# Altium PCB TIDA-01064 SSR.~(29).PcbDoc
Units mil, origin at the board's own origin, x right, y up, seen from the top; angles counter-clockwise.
Board outline 2700 x 2000 mil, 2 copper layers (Top Layer, Bottom Layer), stack 62 mil thick; 76 components, 26 nets, 146 pads, 43 vias.
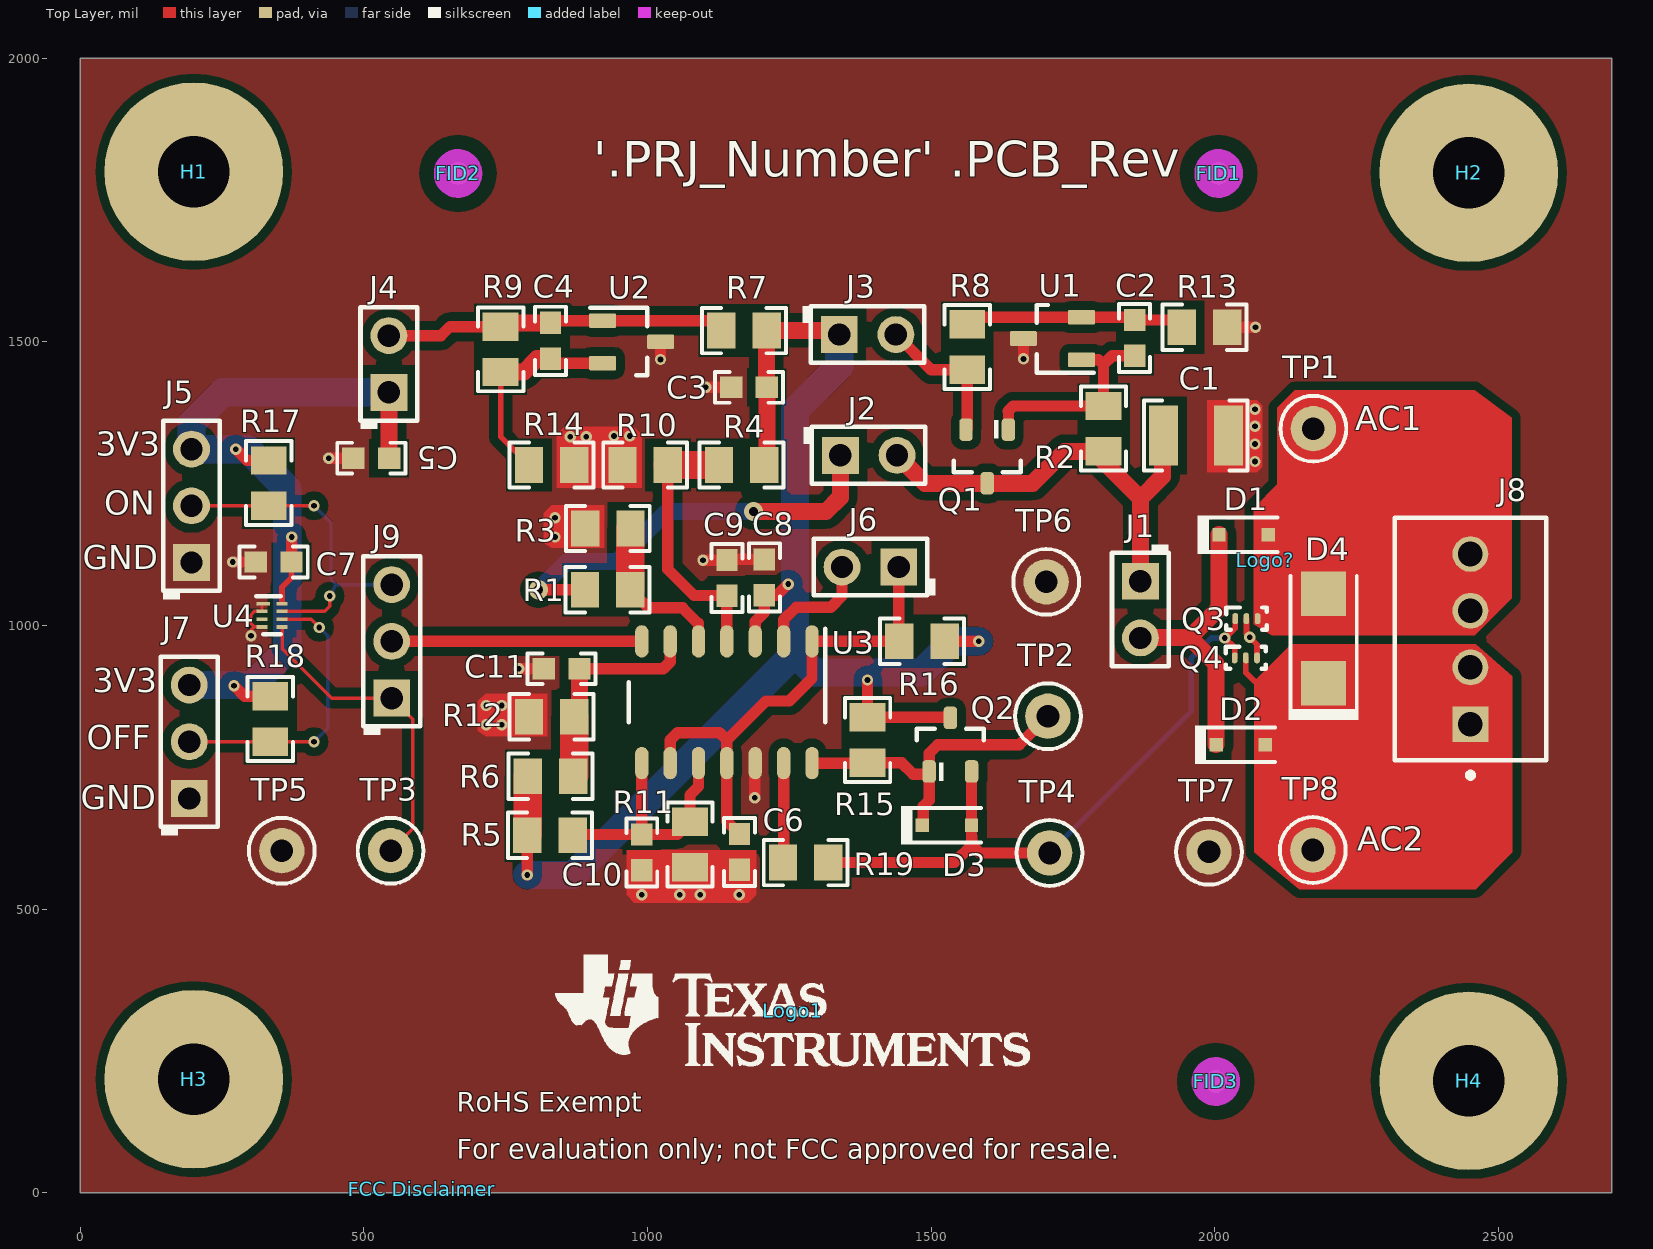
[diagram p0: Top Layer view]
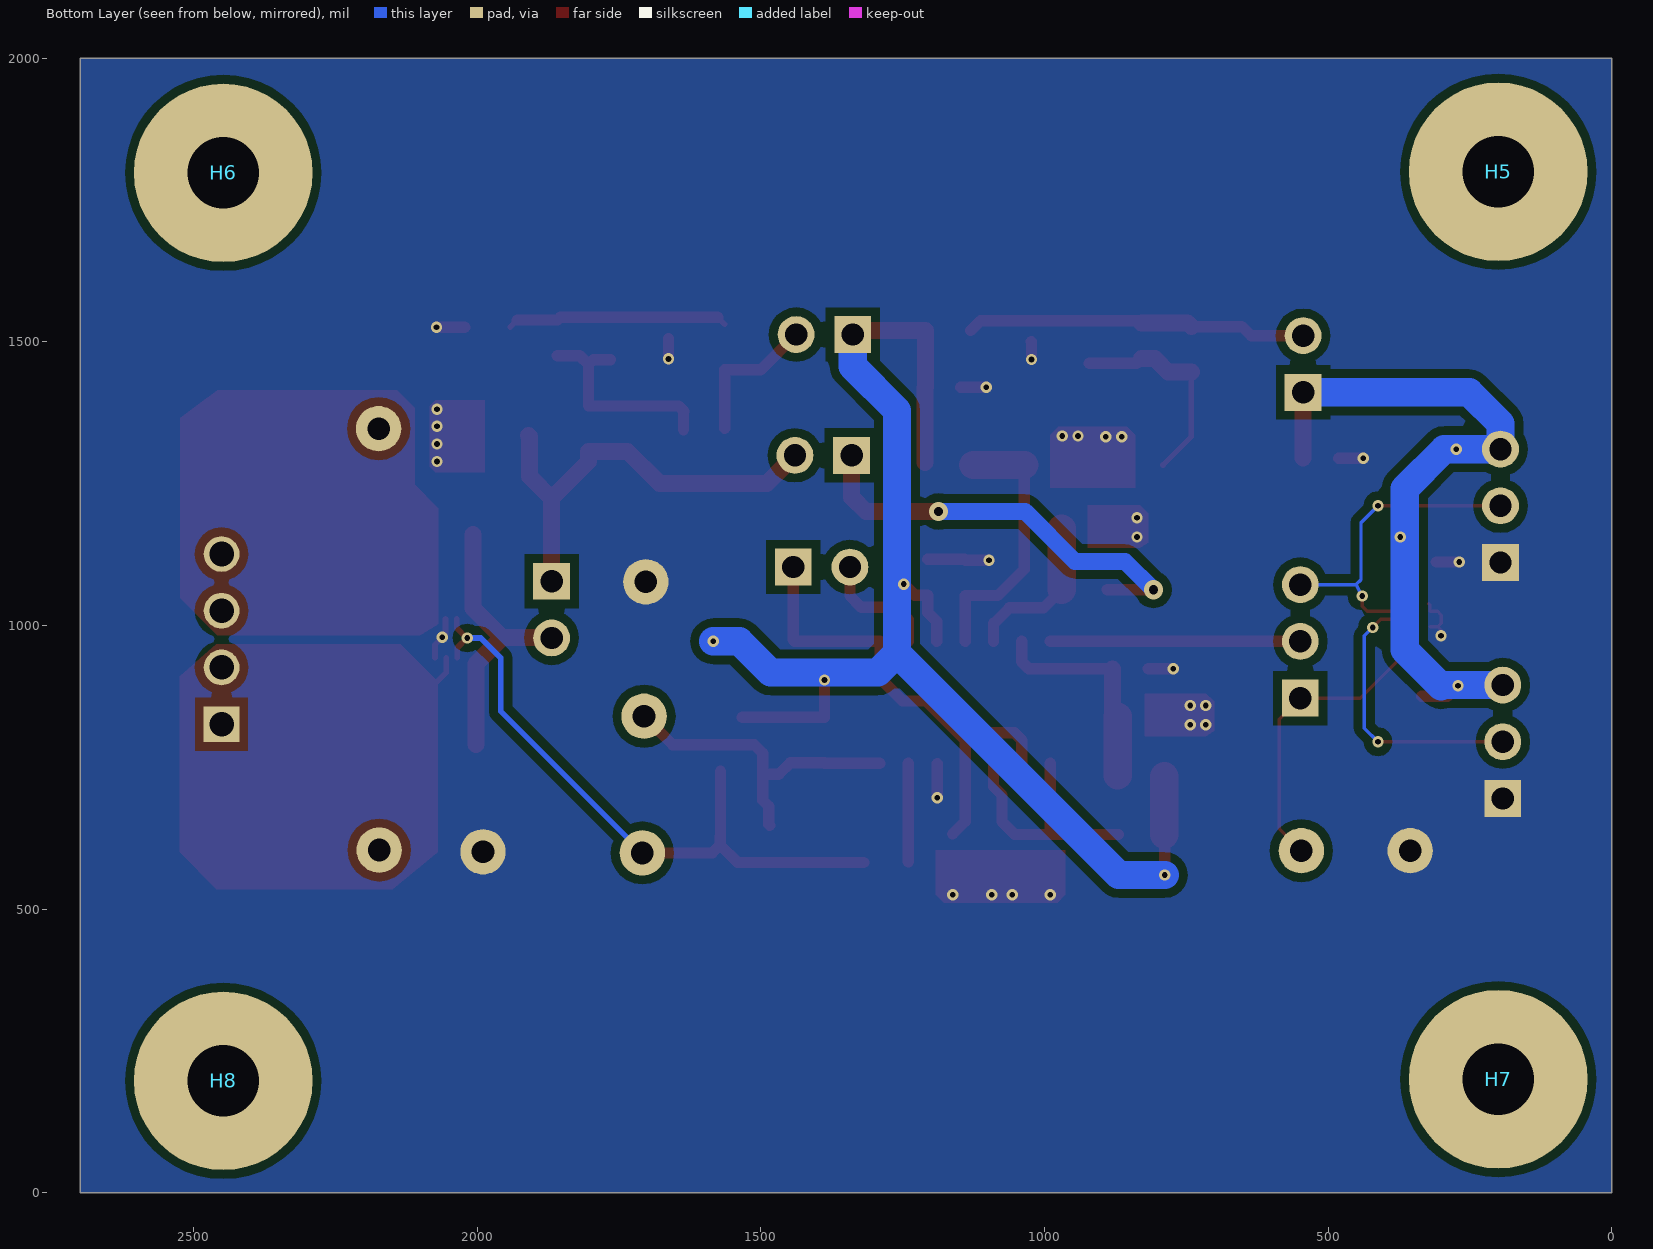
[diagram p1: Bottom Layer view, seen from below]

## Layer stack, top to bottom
Top Solder: solder mask 0.4, Solder Resist, Dk 3.5
Top Layer: signal copper 1.4
Dielectric1: core 59.2, FR-4, Dk 4.8
Bottom Layer: signal copper 1.4
Bottom Solder: solder mask 0.4, Solder Resist, Dk 3.5

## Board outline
0,0 2700,0 2700,2000 0,2000

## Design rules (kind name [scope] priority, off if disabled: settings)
AcuteAngle [All] p1: minimum=4.50000000000000E+0001 checktracksonly=FALSE
AssemblyTestPointUsage [All] p1: valid=2
Clearance Clearance_BoardEdge_MountingHoles [OnCopper and InComponentClass('Mounting Holes') vs IsKeepOut] p1: gap=25
Clearance Clearance_BoardEdge_Poly [OnCopper and InPoly vs IsKeepOut] p2: gap=25
Clearance Clearance_BoardEdge [OnCopper and Not InComponentClass('Logo') and not InComponentClass('FiducialMark') and not InRegion(1000,500,4000,800) and Not IsKeepout vs IsKeepOut] p3: gap=25
Clearance Clearance_Poly [InPolygon] p4: gap=15
Clearance [All] p5: gap=7
ComponentClearance ComponentClearance_Shunt [InComponentClass('Header') vs InComponentClass('Shunt')] p1: gap=0 collisioncheckmode=3 verticalgap=0 showdistances=FALSE
ComponentClearance ComponentClearance_Logo [InComponentClass('Logo')] p2: gap=50 collisioncheckmode=3 verticalgap=10 showdistances=FALSE
ComponentClearance ComponentClearance_ScrewToNut [(HasFootprint('NY PMS 440 0025 PH')) vs (HasFootprint('Keystone_1902C'))] p3: gap=5 collisioncheckmode=3 verticalgap=10 showdistances=FALSE
ComponentClearance ComponentClearance_MountingHoles [InComponentClass('Mounting Holes')] p4: gap=250 collisioncheckmode=3 verticalgap=100000 showdistances=FALSE
ComponentClearance ComponentClearance_SmallPassives [HasFootprint('0201*') or HasFootprint('0402*') or HasFootprint('0508') or HasFootprint('0603*') or HasFootprint('0612') or HasFootprint('0805*') or HasFootprint('0815*') or HasFootprint('0830*') or HasFootprint('1206*') or HasFootprint('1210*') or HasFootprint('1808*') or HasFootprint('1812*') or HasFootprint('1825*') or HasFootprint('2010*') or HasFootprint('2220*') or HasFootprint('2225*') or HasFootprint('2512*') or HasFootprint('2728*') or HasFootprint('3518*') vs HasFootprint('0201*') or HasFootprint('0402*') or HasFootprint('0508') or HasFootprint('0603*') or HasFootprint('0612') or HasFootprint('0805*') or HasFootprint('0815*') or HasFootprint('0830*') or HasFootprint('1206*') or HasFootprint('1210*') or HasFootprint('1808*') or HasFootprint('1812*') or HasFootprint('1825*') or HasFootprint('2010*') or HasFootprint('2220*') or HasFootprint('2225*') or HasFootprint('2512*') or HasFootprint('2728*') or HasFootprint('3518*')] p5: gap=15 collisioncheckmode=3 verticalgap=10 showdistances=FALSE
ComponentClearance ComponentClearance_THtoSMT [IsThruComponent vs IsSMTComponent] p6: gap=50 collisioncheckmode=3 verticalgap=30 showdistances=FALSE
ComponentClearance ComponentClearance_THtoTH [IsThruComponent vs IsThruComponent] p7: gap=50 collisioncheckmode=3 verticalgap=30 showdistances=FALSE
ComponentClearance [All] p8: gap=40 collisioncheckmode=3 verticalgap=10 showdistances=FALSE
DiffPairsRouting [All] p1: maxlimit=100 minlimit=10 mostfreqgap=10 toplayer_minwidth=15 toplayer_maxwidth=15 toplayer_prefwidth=15 bottomlayer_minwidth=15 bottomlayer_maxwidth=15 bottomlayer_prefwidth=15 maxuncoupledlength=1000
FabricationTestPointUsage TestPointUsage [All] p1: valid=2 allowmultiple=FALSE
FabricationTestpoint Testpoint [All] p1: side=3 testpointundercomponent=TRUE minsize=40 maxsize=100 preferedsize=60 minholesize=0 maxholesize=40 preferedholesize=32 testpointgrid=1 allowsidetop=TRUE allowsidebottom=TRUE usegrid=TRUE gridtolerance=0.01
FanoutControl Fanout_LCC [IsLCC] p1: bgadir=Out bgaviamode=Centered fanoutstyle=Auto fanoutdirection=Alternating viagrid=1 // Fanout_LCC (Default Rule)
FanoutControl Fanout_BGA [IsBGA] p2: bgadir=Out bgaviamode=Centered fanoutstyle=Auto fanoutdirection=Alternating viagrid=1 // Fanout_BGA (Default Rule)
FanoutControl Fanout_Default [All] p4: bgadir=Out bgaviamode=Centered fanoutstyle=Auto fanoutdirection=Alternating viagrid=1 // Fanout_Default (Default Rule)
FanoutControl Fanout_Small [(CompPinCount < 5)] p5: bgadir=Out bgaviamode=Centered fanoutstyle=Auto fanoutdirection=OutThenIn viagrid=1 // Fanout_Small (Default Rule)
HoleSize [All] p1: absolutevalues=TRUE maxlimit=251 minlimit=8 maxpercent=80.000 minpercent=20.000
MinimumAnnularRing MinimumAnnularRing_ThermalPadVias [IsVia and InAnyComponent] p1: minimumring=5.91
MinimumAnnularRing [All] p2: minimumring=9
MinimumSolderMaskSliver MinimumSolderMaskSliver_Logo [InComponentClass('Logo') vs InComponentClass('Logo')] p1: minsoldermaskwidth=0.7
MinimumSolderMaskSliver [All] p2: minsoldermaskwidth=3.94
PlaneClearance [All] p1: clearance=15
PlaneConnect [All] p1: planeconnectstyle=Direct reliefexpansion=10 reliefentries=4 reliefconductorwidth=10 reliefairgap=10
PolygonConnect [All] p1: connectstyle=Direct reliefconductorwidth=10 reliefentries=4 polygonreliefangle="90 Angle" airgapwidth=10
RoutingVias ThermalPadVias [IsVia and InAnyComponent] p1: holewidth=7.87 width=19.68 viastyle="Through Hole" minholewidth=7.87 minwidth=19.68 maxholewidth=12.99 maxwidth=23.62
RoutingVias [All] p2: holewidth=16 width=34 viastyle="Through Hole" minholewidth=7.87 minwidth=26 maxholewidth=40 maxwidth=65
SMDToCorner [All] p1: distance=30000
SilkToBoardRegionClearance [Not ((IsComment or IsDesignator) And (Hide <> 'False')) and not InRegion(1000,500,4000,800)] p1:
SilkToSilkClearance [All] p1: silktosilkclearance=0
SilkToSolderMaskClearance SilkscreenOverComponentPads [IsPad] p1: minsilkscreentomaskgap=0 clearancetoexposedcopper=TRUE
SolderMaskExpansion [All] p1: expansion=1.97
Width [All] p1: maxlimit=100 minlimit=6 preferedwidth=10 checkconnectedcopper=TRUE
14 further rules are at their usual default settings.

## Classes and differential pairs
component class AssemblyNote: ZZ1 ZZ2 ZZ3
component class FiducialMark: FID1 FID2 FID3
component class "TIDA-01064 SSR_TID_Hardware": "FCC Disclaimer" FID1 FID2 FID3 H1 H2 H3 H4 H5 H6 H7 H8 Logo1 Logo? ZZ1 ZZ2 ZZ3
component class Logo: Logo1
component class "Mounting Holes": H1 H2 H3 H4
component class Header: J1 J2 J3 J4 J5 J6 J7 J9
component class "TIDA-01064 SSR_Relay": C1 C2 C3 C4 C5 C6 C7 C8 C9 C10 C11 D1 D2 D3 D4 J1 J2 J3 J4 J5 J6 J7 J8 J9 Q1 Q2 Q3 Q4 R1 R2 R3 R4 R5 R6 R7 R8 R9 R10 R11 R12 R13 R14 R15 R16 R17 R18 R19 TP1 TP2 TP3 TP4 TP5 TP6 TP7 TP8 U1 U2 U3 U4

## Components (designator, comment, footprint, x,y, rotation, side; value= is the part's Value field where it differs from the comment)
C1 "C3225X7S2A335M200AB" 1210 1967,1335 r0 top
C2 "GRM1885C1H201JA01D" 0603 1859,1507 r90 top
C3 "GRM188R61E105KA12D" 0603 1179,1420 r180 top
C4 "GRM1885C1H201JA01D" 0603 829,1502 r270 top
C5 "GRM188R61E105KA12D" 0603 513,1295 r180 top
C6 "GRM188R61E105KA12D" 0603 1162,601 r270 top
C7 "GRM188R71C104KA01D" 0603 341,1112 r0 top
C8 "GRM188R71C104KA01D" 0603 1206,1085 r270 top
C9 "GRM188R71C104KA01D" 0603 1140,1084 r270 top
C10 "GRM188R71C104KA01D" 0603 990,600 r90 top
C11 "GRM188R71C104KA01D" 0603 848.68,923.69 r0 top
D1 "1N4448WX-TP" sod-323 2051,1160 r0 top
D2 "1N4448WX-TP" sod-323 2046,790 r0 top
D3 "1N4448WX-TP" sod-323 1528,648 r0 top
D4 "SMAJ40CA" SMA 2192,977 r90 top
"FCC Disclaimer" "FCC disclaimer" FCC_disclaimer 603,7 r90 top
FID1 "Fiducial" Fiducial10-20 2007,1797 r0 top
FID2 "Fiducial" Fiducial10-20 666,1797 r0 top
FID3 "Fiducial" Fiducial10-20 2002,196 r0 top
H1 "NY PMS 440 0025 PH" "NY PMS 440 0025 PH" 200,1800 r0 top locked
H2 "NY PMS 440 0025 PH" "NY PMS 440 0025 PH" 2448,1798 r0 top locked
H3 "NY PMS 440 0025 PH" "NY PMS 440 0025 PH" 200,200 r0 top locked
H4 "NY PMS 440 0025 PH" "NY PMS 440 0025 PH" 2448,197 r0 top locked
H5 "1902C" Keystone_1902C 200,1800 r180 bottom locked
H6 "1902C" Keystone_1902C 2448,1798 r180 bottom locked
H7 "1902C" Keystone_1902C 200,200 r180 bottom locked
H8 "1902C" Keystone_1902C 2448,197 r180 bottom locked
J1 "5-146278-2" TE_5-146278-2 1869,1028 r270 top
J2 "5-146278-2" TE_5-146278-2 1390,1300 r0 top
J3 "5-146278-2" TE_5-146278-2 1388,1513 r0 top
J4 "5-146278-2" TE_5-146278-2 544,1461 r90 top
J5 "5-146278-3" TE_5-146278-3 196.02,1211 r90 top
J6 "5-146278-2" TE_5-146278-2 1393,1103 r180 top
J7 "5-146278-3" TE_5-146278-3 192.02,795 r90 top
J8 "282834-4" TEC_282834-4 2451,976 r90 top
J9 "5-146278-3" TE_5-146278-3 549,972 r90 top
Logo1 "Texas Instruments" TI_Stacked_Overlay_Small 1256,321 r0 top
Logo? "EU RoHS Exempt Logo" EURoHS_Exempt_60mil 2089,1115 r90 top
Q1 "MMBTA05LT1G" SOT-23 1599,1298 r270 top
Q2 "MMBT3904LT1G" SOT-23 1534,790 r90 top
Q3 "CSD18541F5" YJK0003A 2056,1012 r0 top
Q4 "CSD18541F5" YJK0003A 2055,943 r0 top
R1 "CRCW080510M0FKEA" 0805_HV 929.71,1063 r0 top
R2 "CRCW0805205KFKEA" 0805_HV 1804,1347 r270 top
R3 "CRCW08053M09FKEA" 0805_HV 930,1171 r0 top
R4 "CRCW080510M0FKEA" 0805_HV 1166,1283 r0 top
R5 "CRCW080510M0FKEA" 0805_HV 828,630 r180 top
R6 "RC0805JR-0733ML" 0805_HV 829,734 r180 top
R7 "CRCW0805100KFKEA" 0805_HV 1170,1520 r0 top
R8 "CRCW08053M74FKEA" 0805_HV 1564,1491 r270 top
R9 "CRCW0805806KFKEA" 0805_HV 741,1487 r90 top
R10 "CRCW08057M50FKEA" 0805_HV 996,1283 r0 top
R11 "CRCW08054M32FKEA" 0805_HV 1075,614 r90 top
R12 "CRCW08056M49FKEA" 0805_HV 831,839 r0 top
R13 "CRCW08051M30FKEA" 0805_HV 1982,1526 r180 top
R14 "CRCW08052M80FKEA" 0805_HV 831,1283 r180 top
R15 "CRCW080590K9FKEA" 0805_HV 1388,798 r90 top
R16 "CRCW08051M82FKEA" 0805_HV 1484,972 r0 top
R17 "CRCW0805124KFKEA" 0805_HV 332,1251 r90 top
R18 "CRCW0805124KFKEA" 0805_HV 335,835 r90 top
R19 "CRCW08050000Z0EA" 0805_HV 1279,582 r0 top
TP1 "5001" Keystone5001 2174,1347 r0 top
TP2 "5001" Keystone5001 1706,840 r0 top
TP3 "5001" Keystone5001 547.18,602.88 r0 top
TP4 "5001" Keystone5001 1709,599 r0 top
TP5 "5001" Keystone5001 355.18,602.88 r0 top
TP6 "5001" Keystone5001 1703,1077 r0 top
TP7 "5001" Keystone5001 1990,601 r0 top
TP8 "5001" Keystone5001 2173,604 r0 top
U1 "ATL431AIDBZR" DBZ0003A_M 1714,1506 r180 top
U2 "ATL431AIDBZR" DBZ0003A_M 972,1500 r0 top
U3 "LP339D" D0014A_N 1140,864.68 r270 top
U4 "SN74AUP1G74DQER" DQE0008A 338,1018 r0 top
ZZ1 "These assemblies are ESD sensitive, ESD precautions shall be observed." AssemblyNote 185,3829.11 r0 top
ZZ2 "These assemblies must be clean and free from flux and all contaminants. Use of no clean flux is not acceptable." AssemblyNote 185,3740.56 r0 top
ZZ3 "These assemblies must comply with workmanship standards IPC-A-610 Class 2, unless otherwise specified." AssemblyNote 185,3652 r0 top

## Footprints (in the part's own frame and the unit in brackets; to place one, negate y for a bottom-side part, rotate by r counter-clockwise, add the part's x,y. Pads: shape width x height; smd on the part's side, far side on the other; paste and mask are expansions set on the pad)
0603 [mm] "0603 from SM-752 data"
  rect 1x0.95 smd: 1(-0.8,0) 2(0.8,0)
  silkscreen extent -1.52,-0.69 1.52,0.69, body extent -0.87,-0.47 0.87,0.47, height 1
0805_HV [mil] "0805 with 30mil clearance between pads"
  rect 50x63 smd: 1(-40,0) 2(40,0)
  silkscreen extent -74,-40 74,40, body extent -43,-29 43,29, height 57
1210 [mm] "1210 from SM-752 data"
  rect 1.3x2.7 smd: 1(-1.45,0) 2(1.45,0)
  silkscreen extent -2.32,-1.57 2.32,1.57, body extent -1.7,-1.35 1.7,1.35, height 1.35
AssemblyNote [mil] "Assembly Note"
D0014A_N [mm] "SOIC, 14-Leads, Body 8.7x3.9mm, Pitch 1.27mm, IPC Medium Density"
  oval 1.45x0.6 smd: 1(-2.725,3.81) 2(-2.725,2.54) 3(-2.725,1.27) 4(-2.725,0) 5(-2.725,-1.27) 6(-2.725,-2.54) 7(-2.725,-3.81) 8(2.725,-3.81) 9(2.725,-2.54) 10(2.725,-1.27) 11(2.725,0) 12(2.725,1.27) 13(2.725,2.54) 14(2.725,3.81)
  silkscreen extent -3.3,-4.4 0.9,4.4, body extent -3.02,-4.32 3.02,4.32, height 1.6
DBZ0003A_M [mm] "SOT23, 3-Leads, Body 2.9x1.3mm, Pitch 0.95mm, Lead Span 2.4mm, IPC Low Density"
  rrect15% 1.2x0.65 smd: 1(-1.3,0.95) 2(-1.3,-0.95) 3(1.3,0)
  silkscreen extent -1.85,-1.5 0.7,1.53, body extent -1.26,-1.46 1.26,1.46, height 0.98
DQE0008A [mm] "SON, 8-Leads, Body 1.4x1mm, Pitch 0.35mm, TI Recommended"
  rect 0.6x0.16 smd mask+0: 1(-0.4,0.525)
  rect 0.5x0.16 smd mask+0: 2(-0.45,0.175) 3(-0.45,-0.175) 4(-0.45,-0.525) 5(0.45,-0.525) 6(0.45,-0.175) 7(0.45,0.175) 8(0.45,0.525)
  silkscreen extent -0.7,-0.85 0.4,0.85, body extent -0.53,-0.72 0.53,0.73, height 0.41
EURoHS_Exempt_60mil [mil] "EU RoHS Exempt symbol"
FCC_disclaimer [mil]
Fiducial10-20 [mm]
  round 1 smd mask+0.5: 1(0,0)
  Top Layer keep-out circle w1.178: c0,0 r0.5
Keystone5001 [mil] "For Keystone 500x miniature loop terminals"
  round 80 hole 40: 1(0,0)
  silkscreen extent -58,-58 58,58, body extent -49,-49 49,49, height 182
Keystone_1902C [mil] "Hex Standoff, 4-40 threaded, nylon"
  body extent -145,-126 146,126, height 501
"NY PMS 440 0025 PH" [mm] "4-40 nylon screw and mounting hole"
  round 8 hole 3.2: 1(0,0)
  body extent -3.3,-3.3 3.3,3.3, height 2.69
SMA [mm] "Molded Diode, 2-Leads, Body 4.3x2.6mm, IPC Medium Density, based on OnSemi component dimensions and land pattern"
  rect 2x2 smd: 1(-2,0) 2(2,0)
  silkscreen extent -3.66,-1.57 2.79,1.57, body extent -2.6,-1.3 2.6,1.3, height 2.42
sod-323 [mm] "NXP recommended land pattern"
  rect 0.6x0.6 smd paste-0.05: 1(-1.1,0) 2(1.1,0)
  silkscreen extent -2.06,-0.86 1.53,0.86, body extent -1.3,-0.67 1.3,0.68, height 1.1
SOT-23 [mm] "SOT23, 3-Leads, Body 2.9x1.3mm, Pitch 0.95mm, Lead Span 2.5mm, IPC Medium Density"
  rrect50% 1x0.6 smd: 1(-1.2,0.95) 2(-1.2,-0.95) 3(1.2,0)
  silkscreen extent -1.63,-1.5 0.7,1.5, body extent -1.16,-1.45 1.21,1.45, height 1
TE_5-146278-2 [mm] "TE CONNECTIVITY"
  rect 1.65x1.65 hole 1: 1(-1.27,0)
  round 1.65 hole 1: 2(1.27,0)
  silkscreen extent -2.92,-1.27 2.54,1.27, body extent -2.41,-1.17 2.41,1.17, height 8.13
TE_5-146278-3 [mm] "TE CONNECTIVITY"
  rect 1.65x1.65 hole 1: 1(-2.54,0)
  round 1.65 hole 1: 2(0,0) 3(2.54,0)
  silkscreen extent -4.19,-1.27 3.81,1.27, body extent -3.68,-1.17 3.68,1.17, height 8.13
TEC_282834-4 [mm] "TEC"
  rect 1.6x1.6 hole 1.1: 1(-3.81,0)
  round 1.6 hole 1.1: 2(-1.27,0) 3(1.27,0) 4(3.81,0)
  silkscreen extent -6.2,-3.4 5.44,3.4, body extent -5.31,-3.25 5.31,3.25, height 10.02
TI_Stacked_Overlay_Small [mil]
  silkscreen extent -418,-98 418,98
YJK0003A [mm] "SMD, 3-Leads, Body 1.49x0.73mm"
  rrect80% 0.25x0.49 smd paste-0.05 mask-0.05: 1(-0.5,0) 2(0,0) 3(0.5,0)
  silkscreen extent -0.9,-0.5 0.9,0.5, body extent -0.75,-0.37 0.74,0.36, height 0.35

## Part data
C1: "CAP, CERM, 3.3 µF, 100 V, +/- 20%, X7S, 1210"
C2 C4: "CAP, CERM, 200 pF, 50 V, +/- 5%, C0G/NP0, 0603"
C3 C5 C6: "CAP, CERM, 1 µF, 25 V, +/- 10%, X5R, 0603"
C7 C8 C9 C10 C11: "CAP, CERM, 0.1 µF, 16 V, +/- 10%, X7R, 0603"
D1 D2 D3: "Diode, Switching, 75 V, 0.25 A, SOD-323"
D4: "Diode, TVS, Bi, 40 V, 400 W, SMA"
"FCC Disclaimer": library part FCC_disclaimer, "FCC_disclaimer"
FID1 FID2 FID3: "Fiducial mark.  There is nothing to buy or mount."
H1 H2 H3 H4: "Machine Screw, Round, #4-40 x 1/4, Nylon, Philips panhead"
H5 H6 H7 H8: "Standoff, Hex, 0.5\"L #4-40 Nylon"
J1 J2 J3 J4 J6: "Header, 100mil, 2x1, Tin, TH"
J5 J7 J9: "Header, 100mil, 3x1, Tin, TH"
J8: "Terminal Block, 100mil, 4X1 TH"
Logo1: library part TI_Logo, "Texas Instrument Corporate Signature"
Logo?: library part EURoHS_Exempt
Q1: library part "MMBTA05LT1G, ON Semiconductor", "Transistor, NPN, 60 V, 0.5 A, AEC-Q101, SOT-23"
Q2: library part "MMBT3904LT1G, ON Semiconductor", "Transistor, NPN, 40 V, 0.2 A, SOT-23"
Q3 Q4: "MOSFET, N-CH, 60 V,  A, PICOSTAR-3"
R1 R4 R5: "RES, 10.0 M, 1%, 0.125 W, 0805"
R2: "RES, 205 k, 1%, 0.125 W, 0805"
R3: "RES, 3.09 M, 1%, 0.125 W, 0805"
R6: "RES, 33 M, 5%, 0.125 W, 0805"
R7: "RES, 100 k, 1%, 0.125 W, 0805"
R8: "RES, 3.74 M, 1%, 0.125 W, 0805"
R9: "RES, 806 k, 1%, 0.125 W, 0805"
R10: "RES, 7.50 M, 1%, 0.125 W, 0805"
R11: "RES, 4.32 M, 1%, 0.125 W, 0805"
R12: "RES, 6.49 M, 1%, 0.125 W, 0805"
R13: "RES, 1.30 M, 1%, 0.125 W, 0805"
R14: "RES, 2.80 M, 1%, 0.125 W, 0805"
R15: "RES, 90.9 k, 1%, 0.125 W, 0805"
R16: "RES, 1.82 M, 1%, 0.125 W, 0805"
R17 R18: "RES, 124 k, 1%, 0.125 W, 0805"
R19: "RES, 0, 5%, 0.125 W, 0805"
TP1 TP2 TP3 TP4 TP5 TP6 TP7 TP8: "Test Point, Miniature, Black, TH"
U1 U2: "2.5V Low Iq Adjustable Precision Shunt Regulator, DBZ0003A"
U3: "Quad, Low-Power, General Purpose Differential Comparator, D0014A"
U4: "LOW-POWER SINGLE POSITIVE-EDGE-TRIGGERED D-TYPE FLIP-FLOP WITH CLEAR AND PRESET, DQE0008A"
ZZ1 ZZ2 ZZ3: library part AssemblyNote

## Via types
v1: diameter 20, hole 10, Top Layer to Bottom Layer, 41 vias
v2: diameter 34, hole 16, Top Layer to Bottom Layer, 2 vias

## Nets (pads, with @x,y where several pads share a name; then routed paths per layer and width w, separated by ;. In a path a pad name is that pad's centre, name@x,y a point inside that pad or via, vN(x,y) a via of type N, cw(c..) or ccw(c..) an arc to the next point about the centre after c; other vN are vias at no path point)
3.3V: C5.1 C7.2 J4.1 J5.3 J7.3 R17.2 R18.2 U4.8 | length 1475.9
  Top Layer w10: U4.8@355.72,1041.04 355.72,1067.52 372.5,1084.3 C7.2
  Top Layer w20: v1(271,894) 290,875 R18.2 ; v1(274,1311) 294,1291 R17.2 ; C7.2 372.5,1155.5 v1(373,1156)
  Top Layer w30: J4.1 544,1295.5 C5.1
  Bottom Layer w50: J7.3@193.02,894 J7.3 299,895 301,893 365,957 365,1241 295,1311 v1(274,1311) J5.3 196.02,1355.98 251.04,1411 J4.1
10V: C3.1 C8.2 J3.1 Q2.3 R4.2 R5.2 R6.2 R7.2 R15.2 R16.2 U3.3 | length 2544.4
  Top Layer w10: R5.2 R5.2@789,631 ; U3.3@1189,972.97 U3.3 ; R4.2 R4.2@1210.5,1287.5 ; C3.1@1210,1420.5 C3.1 ; J3.1@1331,1520 J3.1
  Top Layer w20: v1(788,560) R5.2 ; U3.3 1190,1007 1206,1023 C8.2 1228.5,1053.5 v1(1248,1073) ; v1(1388,904) R15.2 Q2.3@1533.24,838 ; R16.2 v1(1584,972)
  Top Layer w30: C3.1@1210,1420.5 R7.2 J3.1@1331,1520 ; R4.2@1210.5,1287.5 C3.1
  Top Layer w50: R5.2@789,631 R6.2
  Bottom Layer w50: v1(788,560) 869,560 1260,951 ; J3.1 1338,1457 1260,1379 1260,951 ; v1(1584,972) 1538,972 1483,917 1294,917 1260,951
GND: C1.2 C3.2 C5.2 C6.2 C7.1 C8.1 C9.1 C10.1 C11.1 J5.1 J7.1 Q3.2 Q4.3 R3.1 R10.1 R11.1 R12.1 R13.1 R14.1 TP5.1 TP6.1 TP7.1 U1.3 U2.3 U3.12 U4.1 U4.2 U4.4 | length 631.8
  Top Layer w6: v1(301,982) 301,992.66 306.3,997.96 ; U4.4 319.65,997.96 306.3,997.96 ; U4.1 320.28,1036.7 U4.2 306.93,1024.89 300.44,1018.4 300.44,1003.82 306.3,997.96
  Top Layer w10: R10.1@956,1280 R10.1 ; v1(1189,696) v1@1190,697 ; Q3.2 2056,985 v1(2062,979) 2074.69,966.31 Q4.3
  Top Layer w20: v1(269,1112) C7.1 ; v1(438,1295) C5.2 ; v1@773.31,923.69 C11.1 ; v1(1023,1469) 1023,1499.82 U2.3 ; v1(1098,1115) 1139.5,1115 C9.1 1141,1116.5 C8.1 ; v1(1103,1420) C3.2 ; v1(1189,696) U3.12@1189,756.4 ; v1@1662.82,1470.18 U1.3 ; R13.1 v1(2072,1526)
  other v1: 990,525 1057,525 1093,525 1162,525 716,825 743,825 716,859 743,859 773,924 837,1156 837,1190 2071,1289 2071,1320 864,1333 892,1333 941,1334 969,1334 2071,1351 2071,1381 1663,1470
HV1: D1.2 D4.2 J8.3 J8.4 Q3.3 TP1.1 | length 0.4
  Top Layer w20: D4.2@2191.74,1056 D4.2
HV2: D2.2 D4.1 J8.1 J8.2 Q4.2 TP8.1 | length 49.2
  Top Layer w10: Q4.2 2055,916.75 2070,901.75
  Top Layer w20: D4.1@2190.74,897 D4.1
NetC1_1: C1.1 J1.1 J2.2 Q1.3 R2.2 | length 791.6
  Top Layer w30: J2.2 1489.24,1250.76 Q1.3 1678.76,1250.76 1735,1307 R2.2 1804,1289 1869,1224 ; J1.1 1869,1224 ; C1.1 1908,1333.09 1908,1263 1869,1224
NetC2_1: C2.1 Q1.1 R2.1 U1.1 | length 381.8
  Top Layer w10: 1636,1378 1636.4,1377.6 ; 1794.6,1468.6 1795,1469
  Top Layer w20: 1636,1378 1645,1387 R2.1 1804,1460 ; Q1.1 1636.4,1377.6 ; U1.1 1794.6,1468.6 ; 1795,1469 1804,1460 ; C2.1 1819.5,1475.5 1804,1460
NetC2_2: C2.2 R8.1 R13.2 U1.2 | length 390.3
  Top Layer w10: R8.1 R8.1@1576.4,1543.4 ; C2.2@1854.09,1543.4 C2.2 ; R13.2@1929.5,1538.5 R13.2
  Top Layer w20: R8.1@1576.4,1543.4 U1.2 C2.2@1854.09,1543.4 ; C2.2 R13.2@1929.5,1538.5
NetC4_1: C4.1 J4.2 R7.1 R9.2 U2.1 | length 609.5
  Top Layer w10: U2.1@916.91,1533.5 U2.1
  Top Layer w20: J4.2 636,1511 652,1527 R9.2 ; C4.1 832.5,1537 U2.1 1112.6,1537.4 R7.1
  Top Layer w30: R9.2 747.5,1533.5 C4.1
NetC4_2: C4.2 R9.1 R14.2 U2.2 | length 377.5
  Top Layer w10: R9.1 741,1333 R14.2
  Top Layer w20: C4.2 836.91,1462.6 U2.2
  Top Layer w30: R9.1 782,1447 805.5,1470.5 C4.2
NetC6_1: C6.1 J6.1 R16.1 U3.1 U3.9 U3.11 | length 870.2
  Top Layer w10: R16.1@1440.71,972 R16.1@1443,974.29 ; J6.1 J6.1@1444,1102
  Top Layer w20: U3.9 1040,798 1053,811 1127,811 1140,798 ; C6.1 1140,654.5 U3.11 1140,798 ; R16.1@1440.71,972 U3.1 1290,907 1250,867 1209,867 1140,798 ; R16.1@1443,974.29 J6.1
NetD1_1: D1.1 D2.1 J1.2 | length 498.2
  Top Layer w30: J1.2 1870,979 1956,979 ; D2.1 2002.69,932.31 1956,979 ; D1.1 2007.69,1094.75 2007.39,1094.45 2007.39,1030.39 1956,979
NetD3_1: D3.1 Q2.1 R15.1 TP2.1 U3.14 | length 583.1
  Top Layer w10: R15.1@1387.4,757.4 R15.1
  Top Layer w20: U3.14 R15.1@1387.4,757.4 ; R15.1 1448,758 1468,738 Q2.1@1496.35,738 ; D3.1 1486,649.31 1486,681 1496.6,691.6 1496.6,737.76 Q2.1@1496.35,738 ; TP2.1 1656,790 1512,790 1497,775 1497,738.65 Q2.1@1496.35,738
NetD3_2: D3.2 Q2.2 Q3.1 Q4.1 R19.2 TP4.1 | length 1143.8
  Top Layer w10: Q4.1 2035.32,960.68 v1(2018,978) 2019,978 2036.32,995.32 Q3.1
  Top Layer w20: R19.2 1541,582 1572,613 ; Q2.2 1571.4,648.09 D3.2 1572,613 ; TP4.1 1586,599 1572,613
  Bottom Layer w10: TP4.1 1959,849 1959,943 1994,978 v1(2018,978)
NetJ2_1: J2.1 R1.1 | length 755.2
  Top Layer w20: v2(808,1063) R1.1
  Top Layer w30: v2(1187,1201) 1315,1201 1340,1226 J2.1
  Bottom Layer w30: v2(808,1063) 858,1113 946,1113 1034,1201 v2(1187,1201)
NetJ3_2: J3.2 Q1.2 R8.2 | length 258.4
  Top Layer w10: Q1.2 Q1.2@1564,1347.65
  Top Layer w20: J3.2 1500,1451 R8.2 Q1.2@1564,1347.65
NetJ6_2: J6.2 U3.2 | length 209.4
  Top Layer w20: U3.2 1240,1010 1262,1032 1323,1032 1343,1052 J6.2
NetJ9_1: J9.1 TP3.1 U4.5 | length 568
  Top Layer w6: U4.5 355.72,959.28 443,872 J9.1 586,835 586,641.71 TP3.1
NetJ9_2: J9.2 U3.7 | length 441
  Top Layer w20: J9.2 U3.7
NetR19_1: R19.1 U3.13 | length 177.2
  Top Layer w10: R19.1 R19.1@1240,583 ; U3.13@1239,756.4 U3.13
  Top Layer w20: R19.1@1240,583 U3.13
OFF#: J7.2 R18.1 U4.6 | length 509.3
  Top Layer w6: J7.2 R18.1 v1(412,795) ; U4.6 406.89,1011.11 v1(421.5,996.5)
  Bottom Layer w6: v1(412,795) 436,819 436,982 v1(421.5,996.5)
ON#: J5.2 J9.3 R17.1 U4.7 | length 598
  Top Layer w6: J5.2 R17.1 v1(412,1211) ; U4.7 430.89,1024.89 440,1034 v1(440,1052)
  Bottom Layer w6: v1(412,1211) 442,1181 442,1081 451,1072 ; v1(440,1052) 451,1072 ; J9.3 451,1072
VREF1: C9.2 R4.1 R10.2 U3.4 | length 475.4
  Top Layer w10: 1120.5,1053 1121,1052.5
  Top Layer w20: R10.2 1036,1099 1082,1053 C9.2 ; U3.4 C9.2@1140,1049.57
  Top Layer w50: R10.2 R4.1
VREF2: C10.2 R5.1 R11.2 U3.8 U3.10 | length 454.5
  Top Layer w10: R5.1 R5.1@869.5,631.5 ; U3.8 U3.8@991.45,755.95
  Top Layer w20: R5.1@869.5,631.5 C10.2 ; U3.8 C10.2 ; U3.10 1090,716 1075,701 R11.2 1052.5,631.5 C10.2
VREF3: C11.2 R6.1 R12.2 U3.6 | length 395.2
  Top Layer w10: R6.1 R6.1@871,736 ; R12.2 R12.2@880.18,848.18
  Top Layer w20: C11.2 1027.69,923.69 1040,936 U3.6
  Top Layer w30: R12.2@880.18,848.18 C11.2
  Top Layer w50: R6.1@871,736 R12.2
VUVLO: R1.2 R3.2 U3.5 | length 284.7
  Top Layer w10: R3.2@969.71,1170.71 R3.2 ; 1089.26,1003.74 1090,1003.74
  Top Layer w20: R1.2 1001.71,1031 1062,1031 1089.26,1003.74 ; U3.5 1090,1003.74
  Top Layer w50: R1.2 R3.2@969.71,1170.71
pads on no net: FID1.1 FID2.1 FID3.1 H1.1 H2.1 H3.1 H4.1 U4.3

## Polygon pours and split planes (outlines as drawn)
GND on Bottom Layer "BOTTOM_LAYER_GND_P006" (solid, remove dead copper, pour order 6): 0,0 2700,0 2700,2000 0,2000
GND on Top Layer "TOP_LAYER_GND_P002" (solid, remove dead copper, pour order 2): 0,0 2700,0 2700,2000 0,2000

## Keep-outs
Keep-Out Layer:
  text ".Layer_Name" at 577,-858.49 h60

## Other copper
Top Layer:
  region net GND: 1178,511 1192,525 1192,604 963,604 963,525 977,511
  region net GND: 701,814 715,805 823,805 823,842 823,880 715,880 701,866
  region net GND: 817,1146 831,1137 924,1137 924,1212 831,1212 817,1198
  region net GND: 854,1350 840,1336 840,1243 990,1243 990,1336 976,1350
  region net GND: 2074,1270 2084,1280 2084,1336 2084,1387.5 2078.75,1392.75 2074,1397.5 2046.69,1397.5 1996.69,1397.5 1986.69,1397.5 1986.69,1387.5 1986.69,1270 2037,1270
  region net HV2: 2149.5,535.25 2070,600.25 2070,901.75 2135,966.75 2460,966.75 2525,910.75 2525,759.75 2525,600.25 2460,535.25 2241,535.25
  region net HV1: 2148,983 2101,983 2068.5,1002 2068.5,1048 2068.5,1207 2110.75,1249.25 2110.75,1384 2141.25,1414.5 2242,1414.5 2458.5,1414.5 2523.5,1366 2523.5,1179.92 2523.5,1048 2458.5,983 2299,983
  text ".Layer_Name" at 577,-858.49 h60
Bottom Layer:
  text ".Layer_Name" at 577,-858.49 h60

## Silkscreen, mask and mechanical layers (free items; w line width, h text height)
Top Overlay:
  text "ON" at -638,2785 h50 r90
  text "'.PRJ_Number' .PCB_Rev" at 904,1770 h108.27
  text "AC1" at 2248,1330 h72.83
  text "3V3" at 27,1285 h72.83
  text "ON" at 42,1181 h72.83
  text "GND" at 4,1085 h72.83
  text "3V3" at 22,868 h72.83
  text "OFF" at 11,768 h72.83
  text "GND" at 1,662 h72.83
  text "AC2" at 2251,589 h72.83
  text ".Layer_Name" at 577,-858.49 h60
Bottom Overlay:
  text ".Layer_Name" at 577,-858.49 h60
Top Paste:
  text ".Layer_Name" at 577,-858.49 h60
Bottom Paste:
  text ".Layer_Name" at 577,-858.49 h60
Top Solder:
  text ".Layer_Name" at 577,-858.49 h60
  text ".Layer_Name" at 577,-858.49 h60
Bottom Solder:
  text ".Layer_Name" at 577,-858.49 h60
Drill Guide:
  text ".Layer_Name" at 577,-858.49 h60
M1 Board Outline:
  the board outline again, w10
  text ".Layer_Name" at 577,-858.49 h60
M2 Board Dimensions:
  rectangle: 125,-400 500,-275
  rectangle: 0,-275 125,-150
  lines w7: 0,-275 1000,-275 ; 125,-400 125,-150 ; 250,-400 250,-150 ; 500,-400 500,-150 ; 750,-400 750,-150 ; 0,-400 0,-150 1000,-150 1000,-400 0,-400
  text ".Layer_Name" at 577,-858.49 h60
M3 3D STEP Top:
  text ".Layer_Name" at 577,-858.49 h60
M4 3D STEP Bottom:
  text ".Layer_Name" at 577,-858.49 h60
M5 Assembly Top:
  lines w10: -292,-930.17 6308,-930.17 ; -292,-726.83 6310,-726.83 ; -292,-523.5 -292,-1133.5 3713,-1133.5 6310,-1133.5 6310,-523.5 -291.5,-523.5 -291.5,-1133.5 1284,-1133.5 ; 2173,-1133.5 2173,-523.5 ; 3440,-726.83 3440,-523.5 ; 4280,-726.83 4280,-523.5 ; 4902,-1140 4902,-937.17
  text "COMPONENTS MARKED 'DNP' SHOULD NOT BE POPULATED." at 1153.5,-318.5 h60
  text "ASSEMBLY VARIANT:" at 1153,-434 h60
  text ".VariantName" at 2189,-434 h60
  text "PCB VIEWED FROM TOP SIDE" at -228.5,-655.67 h60
  text "BOARD #:" at 2248,-655.67 h60
  text ".PRJ_Number" at 2793.5,-655.67 h60
  text "REV:" at 3638,-655.67 h60
  text ".PCB_Rev" at 3929.5,-655.67 h60
  text "SVN REV:" at 4476,-655.67 h60
  text ".VersionControl_RevNumber" at 4982,-655.67 h60
  text "TID #:" at 2248,-859 h60
  text ".TID" at 2793.5,-859 h60
  text "PLOT NAME =" at -228.5,-1064.34 h60
  text ".plot_File_Name" at 577,-1064.34 h60
  text "GENERATED    :" at 2250,-1064.34 h60
  text ".Print_Date" at 3119.5,-1064.34 h60
  text ".Print_Time" at 3848.5,-1064.34 h60
  text "TEXAS INSTRUMENTS" at 5113,-1064.34 h60
M6 Assembly Bottom:
  lines w10: -292.5,-727.33 6309.5,-727.33 ; -290.5,-930.67 6309.5,-930.67 ; 1115.5,-1140.5 1115.5,-937.67 ; 1737.5,-727.33 1737.5,-524 ; 2577.5,-727.33 2577.5,-524 ; 3844.5,-1134 3844.5,-524 ; 4733.5,-1134 6309,-1134 6309,-524 -292.5,-524 -292.5,-1134 2304.5,-1134 6309.5,-1134 6309.5,-524
  text "COMPONENTS MARKED 'DNP' SHOULD NOT BE POPULATED." at 6102,-318 h60
  text ".VariantName" at 5058,-434 h60
  text "ASSEMBLY VARIANT:" at 6097,-434 h60
  text ".VersionControl_RevNumber" at 1035.5,-656.17 h60
  text "SVN REV:" at 1541.5,-656.17 h60
  text ".PCB_Rev" at 2088,-656.17 h60
  text "REV:" at 2379.5,-656.17 h60
  text ".PRJ_Number" at 3224,-656.17 h60
  text "BOARD #:" at 3769.5,-656.17 h60
  text "PCB VIEWED FROM BOTTOM SIDE" at 6246,-656.17 h60
  text ".TID" at 3224,-859.5 h60
  text "TID #:" at 3769.5,-859.5 h60
  text "TEXAS INSTRUMENTS" at 904.5,-1064.84 h60
  text ".Print_Time" at 2169,-1064.84 h60
  text ".Print_Date" at 2898,-1064.84 h60
  text "GENERATED    :" at 3767.5,-1064.84 h60
  text ".plot_File_Name" at 5440.5,-1064.84 h60
  text "PLOT NAME =" at 6246,-1064.84 h60
M9 Title Sheet:
  drawing of 57 lines, arcs and shapes, not listed
  text "1" at 739.84,8036.5 h70
  text "2" at 3235.5,8036.5 h70
  text "3" at 5724.84,8036.5 h70
  text "4" at 8231.51,8036.5 h70
  text "5" at 10730.5,8036.5 h70
  text "6" at 13235.5,8036.5 h70
  text "A" at -416.5,6893.5 h70
  text "A" at 14383.5,6893.5 h70
  text "B" at -416.5,4513.5 h70
  text "B" at 14383.5,4513.5 h70
  text "C" at -416.5,2138.5 h70
  text "C" at 14383.5,2138.5 h70
  text "PROJECT TITLE:" at 11343.5,277.5 h45
  text ".PRJ_Title" at 11393.5,144.17 h70
  text "DESIGNED FOR:" at 11343.5,-23.5 h45
  text ".PRJ_Customer" at 11393.5,-163.5 h70
  text "D" at -416.5,-231.5 h70
  text "D" at 14383.5,-231.5 h70
  text "FILE NAME:" at 11343.5,-323.5 h45
  text ".PCB_File_Name_No_Path" at 11393.5,-443.5 h70
  text "Texas Instruments (TI) and/or its licensors do not warrant the accuracy or completeness of this specification" at 6374,-605.34 h45
  text "ENGINEER:" at 11343.5,-613.5 h45
  text "LAYOUT BY:" at 12848.5,-613.5 h45
  text "or any information contained therein. TI and/or its licensors do not warrant that this design will meet" at 6329.01,-718 h45
  text ".PRJ_Engineer" at 11393.5,-768.49 h70
  text ".PCB_Layout" at 12899,-768.49 h70
  text "the specifications, will be suitable for your application or fit for any particular purpose, or will operate in" at 6329.01,-830.67 h45
  text ".Layer_Name" at 577,-858.49 h60
  text "ALTIUM DESIGNER VERSION:" at 12848.5,-923.5 h45
  text "an implementation. TI and/or its licensors do not warrant that the design is production worthy. You should" at 6329.01,-943.33 h45
  text "completely validate and test your design implementation to confirm the system functionality for your application." at 6374,-1056 h45
  text ".print_Scale" at 11393.5,-1056.83 h70
  text ".Application_BuildNumber" at 12899,-1056.83 h70
  text "1" at 739.84,-1263.5 h70
  text "2" at 3235.5,-1263.5 h70
  text "3" at 5724.84,-1263.5 h70
  text "4" at 8231.51,-1263.5 h70
  text "5" at 10730.5,-1263.5 h70
  text "6" at 13235.5,-1263.5 h70
M10 Fab Notes:
  drawing of 173 lines, arcs and shapes, not listed
  text "DESIGN INFORMATION" at 12378.02,6201 h60
  text "MIN. TRACK WIDTH:" at 11733.46,6021 h60
  text "8" at 12829.7,6021 h60
  text "MIL" at 12984.46,6021 h60
  text "MIN. CLEARANCE:" at 11733.46,5889 h60
  text "0.2" at 12769.7,5889 h60
  text "mm" at 12984.46,5889 h60
  text "MIN. VIA PAD SIZE:" at 11733.46,5757 h60
  text "24" at 12799.71,5757 h60
  text "MIL" at 12984.46,5757 h60
  text "0.05mm (2MIL)" at 12428.46,5615.29 h60
  text "MINIMUM ANNULAR RING" at 11404.23,5611 h60
  text "EXTERNAL" at 13136.46,5611 h60
  text "PER" at 11604.23,5493 h60
  text "IPC-D-275 CLASS 2 LEVEL C" at 11824.23,5493 h60
  text "MIL, HOLES" at 13312.46,5380.71 h60
  text "+/-" at 12920,5380 h60
  text "+/-" at 13774,5380 h60
  text "REGISTRATION TOLERANCES:" at 11404.23,5375 h60
  text "METAL" at 12604,5375 h60
  text "5" at 13180.2,5375 h60
  text "3" at 14013.2,5375 h60
  text "MIL" at 14129.46,5375 h60
  text "+/-" at 13774,5262 h60
  text "HOLE SIZE TOLERANCE (UNLESS OTHERWISE SPECIFIED):" at 11404.23,5257 h60
  text "3" at 14013.2,5257 h60
  text "MIL" at 14129.46,5257 h60
  text "MATERIAL:" at 11329.46,5047.54 h60
  text "FR-4 High Tg" at 12315.9,4907.21 h60
  text "FR-408" at 11750.46,4898.64 h60
  text "OTHER" at 13238.46,4898.64 h60
  text "X" at 12161,4895 h60
  text "62 MIL (1.6mm) +/-10%" at 12070.56,4735.92 h60
  text "THICKNESS:" at 11404.23,4731.64 h60
  text "X" at 11942.4,4731.64 h60
  text "OTHER" at 13355.46,4731.64 h60
  text "TOLERANCE:" at 11404.23,4573.64 h60
  text "X" at 12243.53,4573.64 h60
  text "ANSI IPC-6012 TYPE 3 CLASS 2" at 12430.48,4573.64 h60
  text "OTHER +/-" at 12430.46,4417.64 h60
  text "BOW & TWIST:" at 11404.23,4260.64 h60
  text "X" at 12243.53,4260.64 h60
  text "ANSI IPC-6012 TYPE 3 CLASS 2" at 12430.48,4260.64 h60
  text "OTHER +/-" at 12430.46,4102.13 h60
  text "DRILLING:" at 11329.46,3963.64 h60
  text "REFERENCE:" at 11404.23,3846.64 h60
  text "X" at 12052.46,3846.64 h60
  text "AS SHOWN" at 12239.46,3846.64 h60
  text "X" at 12953.46,3846.64 h60
  text "NC_DRILL FILES" at 13090.46,3846.64 h60
  text "PTH COPPER THICKNESS:" at 11404.23,3688.64 h60
  text "X" at 12534.46,3688.64 h60
  text "20-30 um" at 12671.46,3688.64 h60
  text "OTHER" at 13388.46,3688.64 h60
  text "BOARD FINISH:" at 11329.46,3529.64 h60
  text "SILKSCREEN:" at 11484.68,3411.64 h60
  text "X" at 12433.46,3411.64 h60
  text "TOP" at 12559.46,3411.64 h60
  text "X" at 12943.46,3411.64 h60
  text "BOTTOM" at 13070.46,3411.64 h60
  text "SILKSCREEN COLOR:" at 11484.68,3244.64 h60
  text "X" at 12432.42,3244.64 h60
  text "WHITE" at 12559.46,3244.64 h60
  text "OTHER" at 13070.46,3244.64 h60
  text "X" at 12563.42,3085.44 h60
  text "GREEN" at 12690.46,3085.44 h60
  text "OTHER" at 13308.46,3085.44 h60
  text "SOLDER RESIST COLOR:" at 11484.68,3074.64 h60
  text "X" at 12563.42,2915.44 h60
  text "MATTE" at 12690.46,2915.44 h60
  text "SEMI-GLOSS" at 13308,2914.8 h60
  text "IMMERSION GOLD (ENIG)" at 12390.46,2726.92 h60
  text "ENEPIG" at 13728,2723.64 h60
  text "SURFACE FINISH:" at 11329.46,2722.64 h60
  text "X" at 12203.51,2722.64 h60
  text "IMM. TIN/SILVER OR EQUIV" at 11659,2565.64 h60
  text "OTHER" at 13090.46,2565.64 h60
  text "ARRAY/PANEL:" at 11329.46,2386.64 h60
  text "CUT AND TRIM PER M1 BOARD OUTLINE" at 12390.46,2382.35 h60
  text "N.C. ROUTE" at 12390.46,2230.64 h60
  text "X" at 13069.46,2230.64 h60
  text "V. SCORE" at 13256.46,2230.64 h60
  text "CERTIFICATION:" at 11329.46,2093.64 h60
  text "MATERIALS AND WORKMANSHIP FOR ALL PCBS" at 12054.46,2093.64 h60
  text "TO MEET OR EXCEED THE REQUIREMENTS OF:" at 12054.46,1995.64 h60
  text "X" at 11680.96,1859.13 h60
  text "ANSI IPC-A-600F CLASS ->" at 11819.96,1859.13 h60
  text "X" at 13459.02,1859.13 h60
  text "2" at 13577.96,1859.14 h60
  text "1" at 13262.96,1857.64 h60
  text "3" at 13931.96,1857.64 h60
  text "X" at 12495.02,1699.64 h60
  text "RoHS" at 12631.96,1699.64 h60
  text "OTHER" at 13276.36,1699.64 h60
  text "PER ORDER" at 13673.42,1699.64 h60
  text "ALL BOARDS MUST MEET OR EXCEED UL94-V0 REQUIREMENTS." at 11357,1534 h60
  text "PCB MUST BEAR THE UL94V-0 UL REGISTERED MATERIAL ID NUMBER" at 11357,1414 h60
  text "ADDITIONAL REQUIREMENTS:" at 11329.46,1240.64 h60
  text "MICROSECTION:" at 11404.23,1125.64 h60
  text "YES" at 12309.96,1125.64 h60
  text "REQUIRED" at 13171.46,969.49 h60
  text "BARE BOARD ELEC. TEST:" at 11404.23,966.64 h60
  text "NONE" at 12709.96,966.64 h60
  text "X" at 13044.46,966.64 h60
  text "PER ORDER" at 13763.46,966.64 h60
  text ".Layer_Name" at 577,-858.49 h60
M11 Gerber Information:
  lines w10: -292,-930.17 6308,-930.17 ; -292,-726.83 6310,-726.83 ; -292,-523.5 -292,-1133.5 3713,-1133.5 6310,-1133.5 6310,-523.5 -291.5,-523.5 -291.5,-1133.5 1284,-1133.5 ; 2173,-1133.5 2173,-523.5 ; 3440,-726.83 3440,-523.5 ; 4280,-726.83 4280,-523.5 ; 4902,-1140 4902,-937.17
  text "ALL ARTWORK VIEWED FROM TOP SIDE" at -228.5,-655.67 h60
  text "BOARD #:" at 2248,-655.67 h60
  text ".PRJ_Number" at 2793.5,-655.67 h60
  text "REV:" at 3638,-655.67 h60
  text ".PCB_Rev" at 3929.5,-655.67 h60
  text "SVN REV:" at 4476,-655.67 h60
  text ".VersionControl_RevNumber" at 4982,-655.67 h60
  text "LAYER NAME =" at -228.5,-858.49 h60
  text "TID #:" at 2248,-859 h60
  text ".TID" at 2793.5,-859 h60
  text "PLOT NAME =" at -228.5,-1064.34 h60
  text ".plot_File_Name" at 577,-1064.34 h60
  text "GENERATED    :" at 2250,-1064.34 h60
  text ".Print_Date" at 3119.5,-1064.34 h60
  text ".Print_Time" at 3848.5,-1064.34 h60
  text "TEXAS INSTRUMENTS" at 5113,-1064.34 h60
M12 Stackup:
  drawing of 191 lines, arcs and shapes, not listed
  text "Layer" at 9790.34,7830 h60
  text "Name" at 10200.26,7830 h60
  text "Material" at 11130,7830 h60
  text "Thickness" at 11989.77,7830 h60
  text "Constant" at 12639.6,7830 h60
  text "Board Layer Stack" at 13209.46,7830 h60
  text "1" at 9790.34,7710 h60
  text "Top Overlay" at 10200.26,7710 h60
  text "2" at 9790.34,7590 h60
  text "Top Solder" at 10200.26,7590 h60
  text "Solder Resist" at 11130,7590 h60
  text "0.40mil" at 11989.77,7590 h60
  text "3.5" at 12639.6,7590 h60
  text "3" at 9790.34,7470 h60
  text "Top Layer" at 10200.26,7470 h60
  text "Copper" at 11130,7470 h60
  text "1.40mil" at 11989.77,7470 h60
  text "4" at 9790.34,7350 h60
  text "Dielectric1" at 10200.26,7350 h60
  text "FR-4" at 11130,7350 h60
  text "59.20mil" at 11989.77,7350 h60
  text "4.8" at 12639.6,7350 h60
  text "5" at 9790.34,7230 h60
  text "Bottom Layer" at 10200.26,7230 h60
  text "Copper" at 11130,7230 h60
  text "1.40mil" at 11989.77,7230 h60
  text "6" at 9790.34,7110 h60
  text "Bottom Solder" at 10200.26,7110 h60
  text "Solder Resist" at 11130,7110 h60
  text "0.40mil" at 11989.77,7110 h60
  text "3.5" at 12639.6,7110 h60
  text "7" at 9790.34,6990 h60
  text "Bottom Overlay" at 10200.26,6990 h60
  text ".Layer_Name" at 577,-858.49 h60
M13 Component Bodies Top:
  text ".Layer_Name" at 577,-858.49 h60
M14 Component Bodies Bottom:
  text ".Layer_Name" at 577,-858.49 h60
M15 Courtyards Top:
  text ".Layer_Name" at 577,-858.49 h60
M16 Courtyards Bottom:
  text ".Layer_Name" at 577,-858.49 h60
Drill Drawing:
  circle w10: c5363.72,2644.68 r27.63
  lines w10: 5336.09,2755.19 5349.9,2755.19 5363.72,2741.38 5377.53,2755.19 5391.34,2755.19 5377.53,2769 5391.34,2782.82 5377.53,2782.82 5363.72,2796.63 5349.9,2782.82 5336.09,2782.82 5349.9,2769 5336.09,2755.19 ; 5336.09,2920.95 5391.34,2920.95 5363.72,2865.7 5336.09,2920.95 ; 5336.09,2990.02 5391.34,2990.02 5391.34,3045.27 5336.09,3045.27 5336.09,2990.02 ; 5336.09,3114.34 5363.72,3128.15 5391.34,3114.34 5377.53,3141.96 5391.34,3169.59 5363.72,3155.78 5336.09,3169.59 5349.9,3141.96 5336.09,3114.34 ; 5336.09,3252.47 5349.9,3252.47 5349.9,3238.66 5377.53,3238.66 5377.53,3252.47 5391.34,3252.47 5391.34,3280.1 5377.53,3280.1 5377.53,3293.91 5349.9,3293.91 5349.9,3280.1 5336.09,3280.1 5336.09,3252.47
  lines w12: 5286,2579.76 8517.49,2579.76 ; 5286,3325.68 8517.49,3325.68 ; 5623.86,2455.44 5623.86,3450 ; 5955.86,2455.44 5955.86,3450 ; 6592.43,2455.44 6592.43,3450 ; 6851.57,2455.44 6851.57,3450 ; 7226.72,2455.44 7226.72,3450 ; 7951.05,2455.44 7951.05,3450 ; 5286,2455.44 8517.49,2455.44 8517.49,3450 5286,3450 5286,2455.44
  text "Symbol" at 5360.59,3362.98 h72
  text "Quantity" at 5661.16,3362.98 h72
  text "Finished Hole Size" at 5993.16,3362.98 h72
  text "Plated" at 6629.72,3362.98 h72
  text "Hole Type" at 6888.86,3362.98 h72
  text "Drill Layer Pair" at 7264.02,3362.98 h72
  text "Hole Tolerance" at 7988.35,3362.98 h72
  text "41" at 5661.16,3238.66 h60
  text "10.00mil (0.254mm)" at 5993.16,3238.66 h60
  text "PTH" at 6629.72,3238.66 h60
  text "Round" at 6888.86,3238.66 h60
  text "Top Layer - Bottom Layer" at 7264.02,3238.66 h60
  text "2" at 5661.16,3114.34 h60
  text "16.00mil (0.406mm)" at 5993.16,3114.34 h60
  text "PTH" at 6629.72,3114.34 h60
  text "Round" at 6888.86,3114.34 h60
  text "Top Layer - Bottom Layer" at 7264.02,3114.34 h60
  text "19" at 5661.16,2990.02 h60
  text "39.37mil (1.000mm)" at 5993.16,2990.02 h60
  text "PTH" at 6629.72,2990.02 h60
  text "Round" at 6888.86,2990.02 h60
  text "Top Layer - Bottom Layer" at 7264.02,2990.02 h60
  text "8" at 5661.16,2865.7 h60
  text "40.00mil (1.016mm)" at 5993.16,2865.7 h60
  text "PTH" at 6629.72,2865.7 h60
  text "Round" at 6888.86,2865.7 h60
  text "Top Layer - Bottom Layer" at 7264.02,2865.7 h60
  text "4" at 5661.16,2741.38 h60
  text "43.31mil (1.100mm)" at 5993.16,2741.38 h60
  text "PTH" at 6629.72,2741.38 h60
  text "Round" at 6888.86,2741.38 h60
  text "Top Layer - Bottom Layer" at 7264.02,2741.38 h60
  text "4" at 5661.16,2617.06 h60
  text "125.98mil (3.200mm)" at 5993.16,2617.06 h60
  text "PTH" at 6629.72,2617.06 h60
  text "Round" at 6888.86,2617.06 h60
  text "Top Layer - Bottom Layer" at 7264.02,2617.06 h60
  text "78 Total" at 5661.16,2492.74 h60
  text ".Layer_Name" at 577,-858.49 h60
M17 Embedded Cavity:
  text ".Layer_Name" at 577,-858.49 h60
M18 Embedded Assembly:
  text ".Layer_Name" at 577,-858.49 h60
M19 Embedded Keepout:
  text ".Layer_Name" at 577,-858.49 h60

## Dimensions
0,0 to 2700,0 on M2 Board Dimensions
0,0 to 0,2000 on M2 Board Dimensions
0,-400 to 1000,-400 on M2 Board Dimensions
